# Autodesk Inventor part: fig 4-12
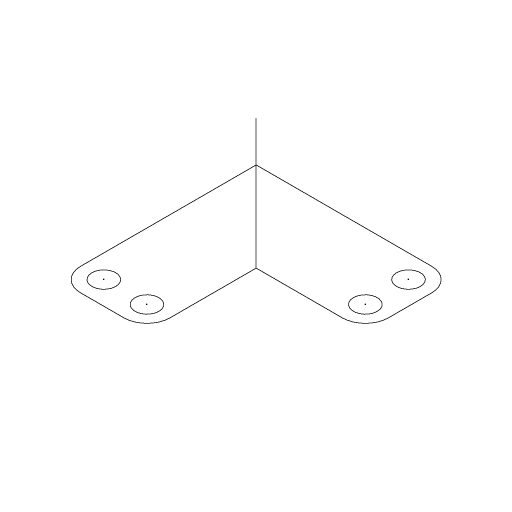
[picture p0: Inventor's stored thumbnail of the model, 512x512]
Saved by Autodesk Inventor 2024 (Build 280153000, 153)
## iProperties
Created: 2005-02
Part Number: fig 4-12
Document SubType Name: Modeling
Designer: CADCIM
Manufacturer: Standard
Standards Organization: Custom
Density: 1 g/cm^3
Material: Generic
Appearance: Default
Author: CADCIM
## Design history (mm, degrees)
sketch "Sketch1"
  geometry: L1 (5.141, 24.979)-(-32.827, 24.979); L2 (-32.827, 24.979)-(-32.827, -12.989); L3 (-27.827, -17.989)-(-18.492, -17.989); L4 (-13.492, -12.989)-(-13.492, 5.644); L5 (-13.492, 5.644)-(5.141, 5.644); L6 (10.141, 10.644)-(10.141, 19.979); L7 (-13.492, 5.644)-(-41.603, 33.755); C1 r 2.58 at (-27.827, -12.989); C2 r 2.58 at (-18.492, -12.989); C3 r 2.58 at (5.141, 10.644); C4 r 2.58 at (5.141, 19.979); A1 r 5 centre (-27.827, -12.989) between (-32.827, -12.989) and (-27.827, -17.989); A2 r 5 centre (-18.492, -12.989) between (-18.492, -17.989) and (-13.492, -12.989); A3 r 5 centre (5.141, 10.644) between (5.141, 5.644) and (10.141, 10.644); A4 r 5 centre (5.141, 19.979) between (10.141, 19.979) and (5.141, 24.979)
  constraints: 14 end point, 8 centre point, 8 point on circle, 8 tangent, 4 equal radius, 4 parallel, 3 perpendicular, 2 coincident, 1 horizontal
